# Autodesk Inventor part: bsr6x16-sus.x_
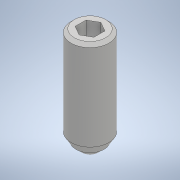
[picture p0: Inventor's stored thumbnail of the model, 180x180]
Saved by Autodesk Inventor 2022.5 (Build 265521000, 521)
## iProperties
Created: 2020-01
Part Number: bsr6x16-sus.x_
Material: 一般
Document SubType Name: Modeling
Designer: ImaoCorp
Density: 1 g/cm^3
Appearance: 既定
Sending System: SOLIDWORKS 2018-2018316
MC: AMD64
MC_MODEL: Intel64 Family 6 Model 60 Stepping 3, GenuineIntel
OS: Windows_NT
FRU: Parasolid Version 30.0, build 310,  6- 8-2018
FORMAT: text
GUISE: transmit
KEY: bsr6x16-sus
FILE: bsr6x16-sus.x_t
DATE: Thu Jan 23 16:47:06 2020
Author: ImaoCorp
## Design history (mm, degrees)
feature "Base1"
node "ソリッド1"
